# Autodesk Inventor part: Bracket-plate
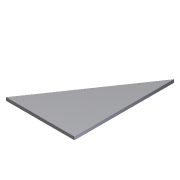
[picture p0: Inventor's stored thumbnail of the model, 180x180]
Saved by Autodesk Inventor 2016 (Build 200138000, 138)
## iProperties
Shininess: 64.0
Length Units: 11269
Angle Units: 11279
Time Units: 11290
Mass Units: 11283
Length Display Precision: 3
Angle Display Precision: 2
Compacted: True
Part Number: Bracket-plate
Document SubType Name: Modeling
Created: 2003-01
Designer: Owner
Density: 1 g/cm^3
Material: Generic
Appearance: Default
Density: 0.0
Volumn: 0.0
Area: 0.0
PropertySet Name: Model Information
Control State: 0
Master: False
Checked Out: False
Author: Owner
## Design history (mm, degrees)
sketch "Sketch1"
  geometry: L1 (-27.627, 0.004)-(-0.127, 0.004); L2 (-0.127, 0.004)-(-0.127, 40.004); L3 (-0.127, 40.004)-(-27.627, 0.004)
  constraints: 6 end point, 1 horizontal, 1 perpendicular
  dimensions: "d0" = 27.5 distance of L1.start L1.end; "d1" = 40 distance of L1.end L2.end
extrude "Extrusion1" new body sketch "Sketch1" distance "d2" = 1.25; taper "d3" = 0 deg
body "Solid1"
